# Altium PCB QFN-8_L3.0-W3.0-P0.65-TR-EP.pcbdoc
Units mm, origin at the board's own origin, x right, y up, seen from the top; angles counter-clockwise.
Board outline 16.14 x 16.83 mm, 2 copper layers (Top Layer, Bottom Layer), stack 0 mm thick; 1 components, 0 nets, 9 pads, 0 vias.
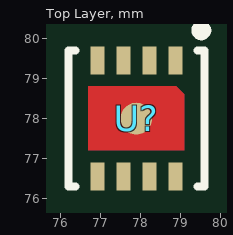
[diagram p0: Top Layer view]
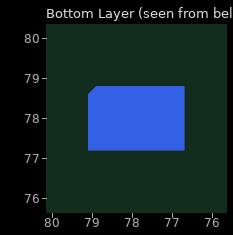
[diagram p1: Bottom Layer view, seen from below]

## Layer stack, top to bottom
Top Layer: signal copper (thickness not stored)
Bottom Layer: signal copper (thickness not stored)

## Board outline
85.994,69.85 69.85,69.85 69.85,86.681 85.994,86.681

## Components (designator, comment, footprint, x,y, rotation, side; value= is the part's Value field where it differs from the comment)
U? "" QFN-8_L3.0-W3.0-P0.65-TR-EP 77.899,78 r0 top

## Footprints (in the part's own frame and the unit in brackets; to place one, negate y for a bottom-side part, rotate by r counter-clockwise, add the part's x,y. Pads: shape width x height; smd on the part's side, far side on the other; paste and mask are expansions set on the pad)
QFN-8_L3.0-W3.0-P0.65-TR-EP [mm]
  rect 0.35x0.7 smd: 1(0.975,1.45) 2(0.325,1.45) 3(-0.325,1.45) 4(-0.975,1.45) 5(-0.975,-1.45) 6(-0.325,-1.45) 7(0.325,-1.45) 8(0.975,-1.45)
  round 0.796 smd: 9(-0.006,-0.004)
  Top Layer region: 1.2,-0.8 -1.2,-0.8 -1.2,0.8 1,0.8 1.2,0.6
  Bottom Layer region: 1.2,-0.8 -1.2,-0.8 -1.2,0.8 1,0.8 1.2,0.6
  Multi-Layer region: 1.2,-0.8 -1.2,-0.8 -1.2,0.8 1,0.8 1.2,0.6
  silkscreen extent -1.7,-1.7 1.75,2.33

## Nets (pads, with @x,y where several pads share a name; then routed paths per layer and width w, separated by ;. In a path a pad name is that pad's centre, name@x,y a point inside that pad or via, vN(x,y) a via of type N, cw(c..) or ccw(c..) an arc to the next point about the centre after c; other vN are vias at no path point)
pads on no net: U?.1 U?.2 U?.3 U?.4 U?.5 U?.6 U?.7 U?.8 U?.9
